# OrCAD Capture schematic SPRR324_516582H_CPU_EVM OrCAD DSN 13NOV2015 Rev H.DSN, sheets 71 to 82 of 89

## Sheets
71 SH78 - TPS57112 -- 1V5 DDR: size B; rev: A; company: Texas Instruments; note: 516172-0001
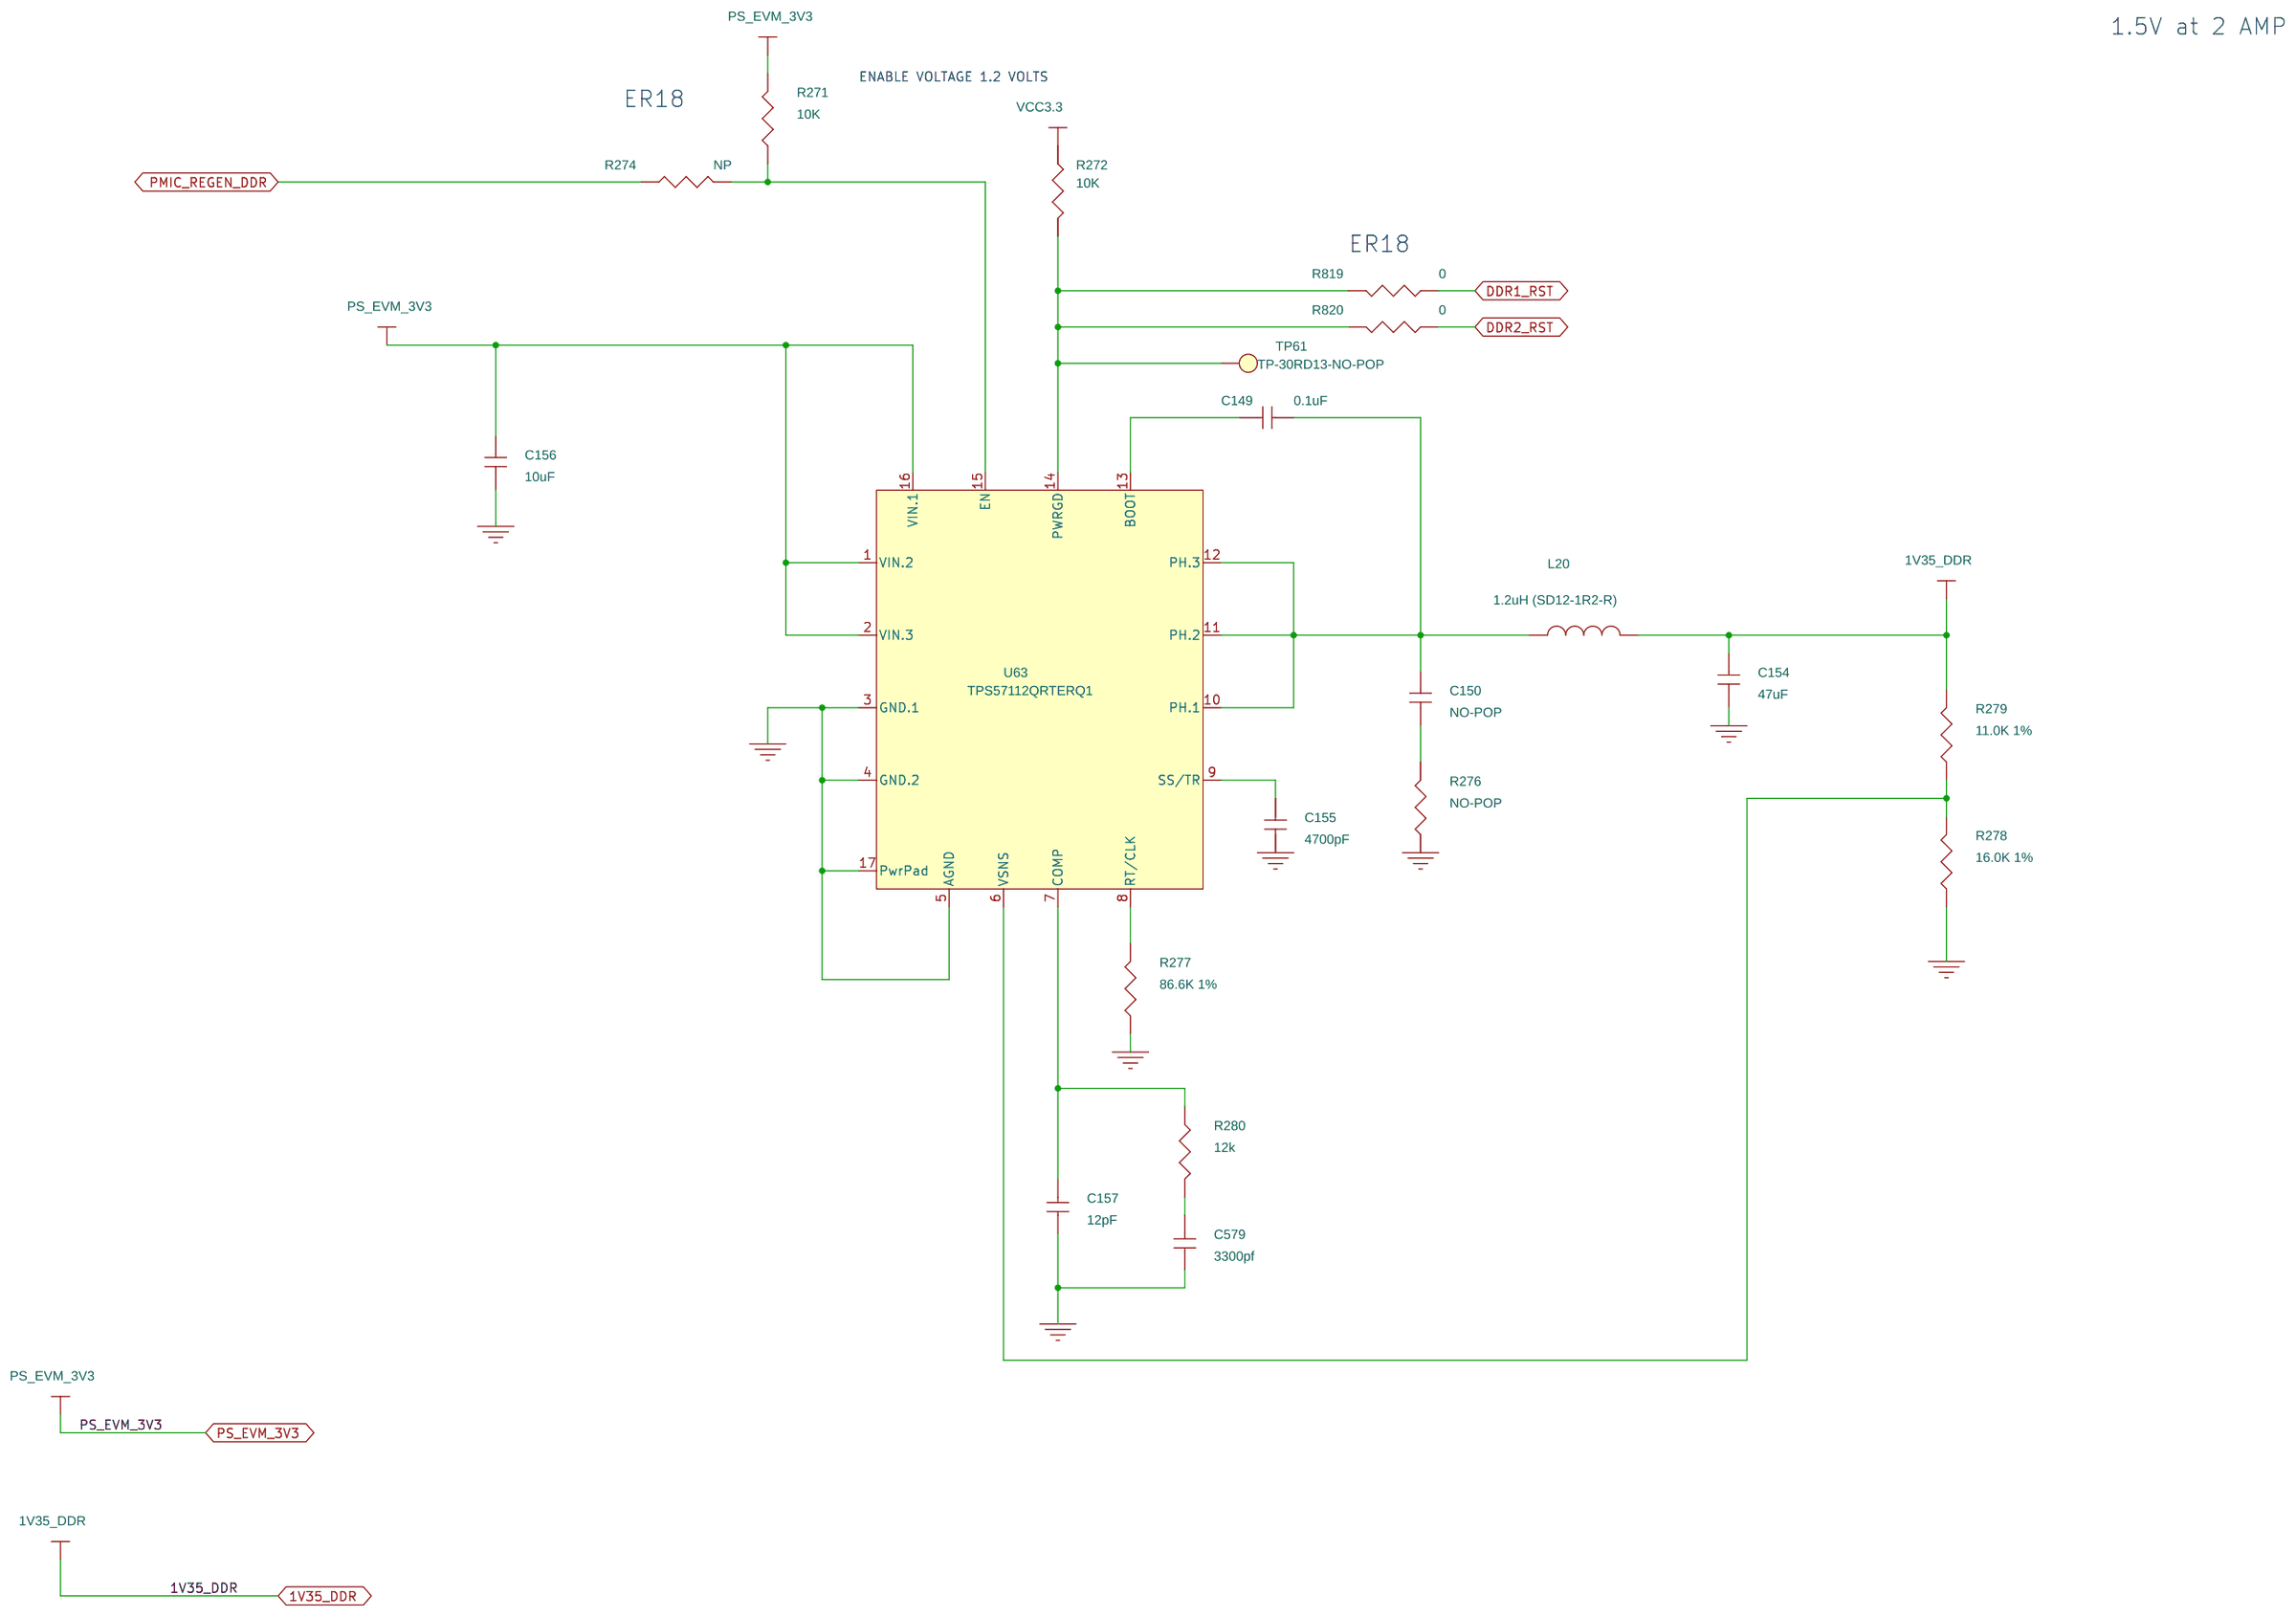
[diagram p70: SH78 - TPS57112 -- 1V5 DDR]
72 SH79 - CORE POWER ROUTER: size B
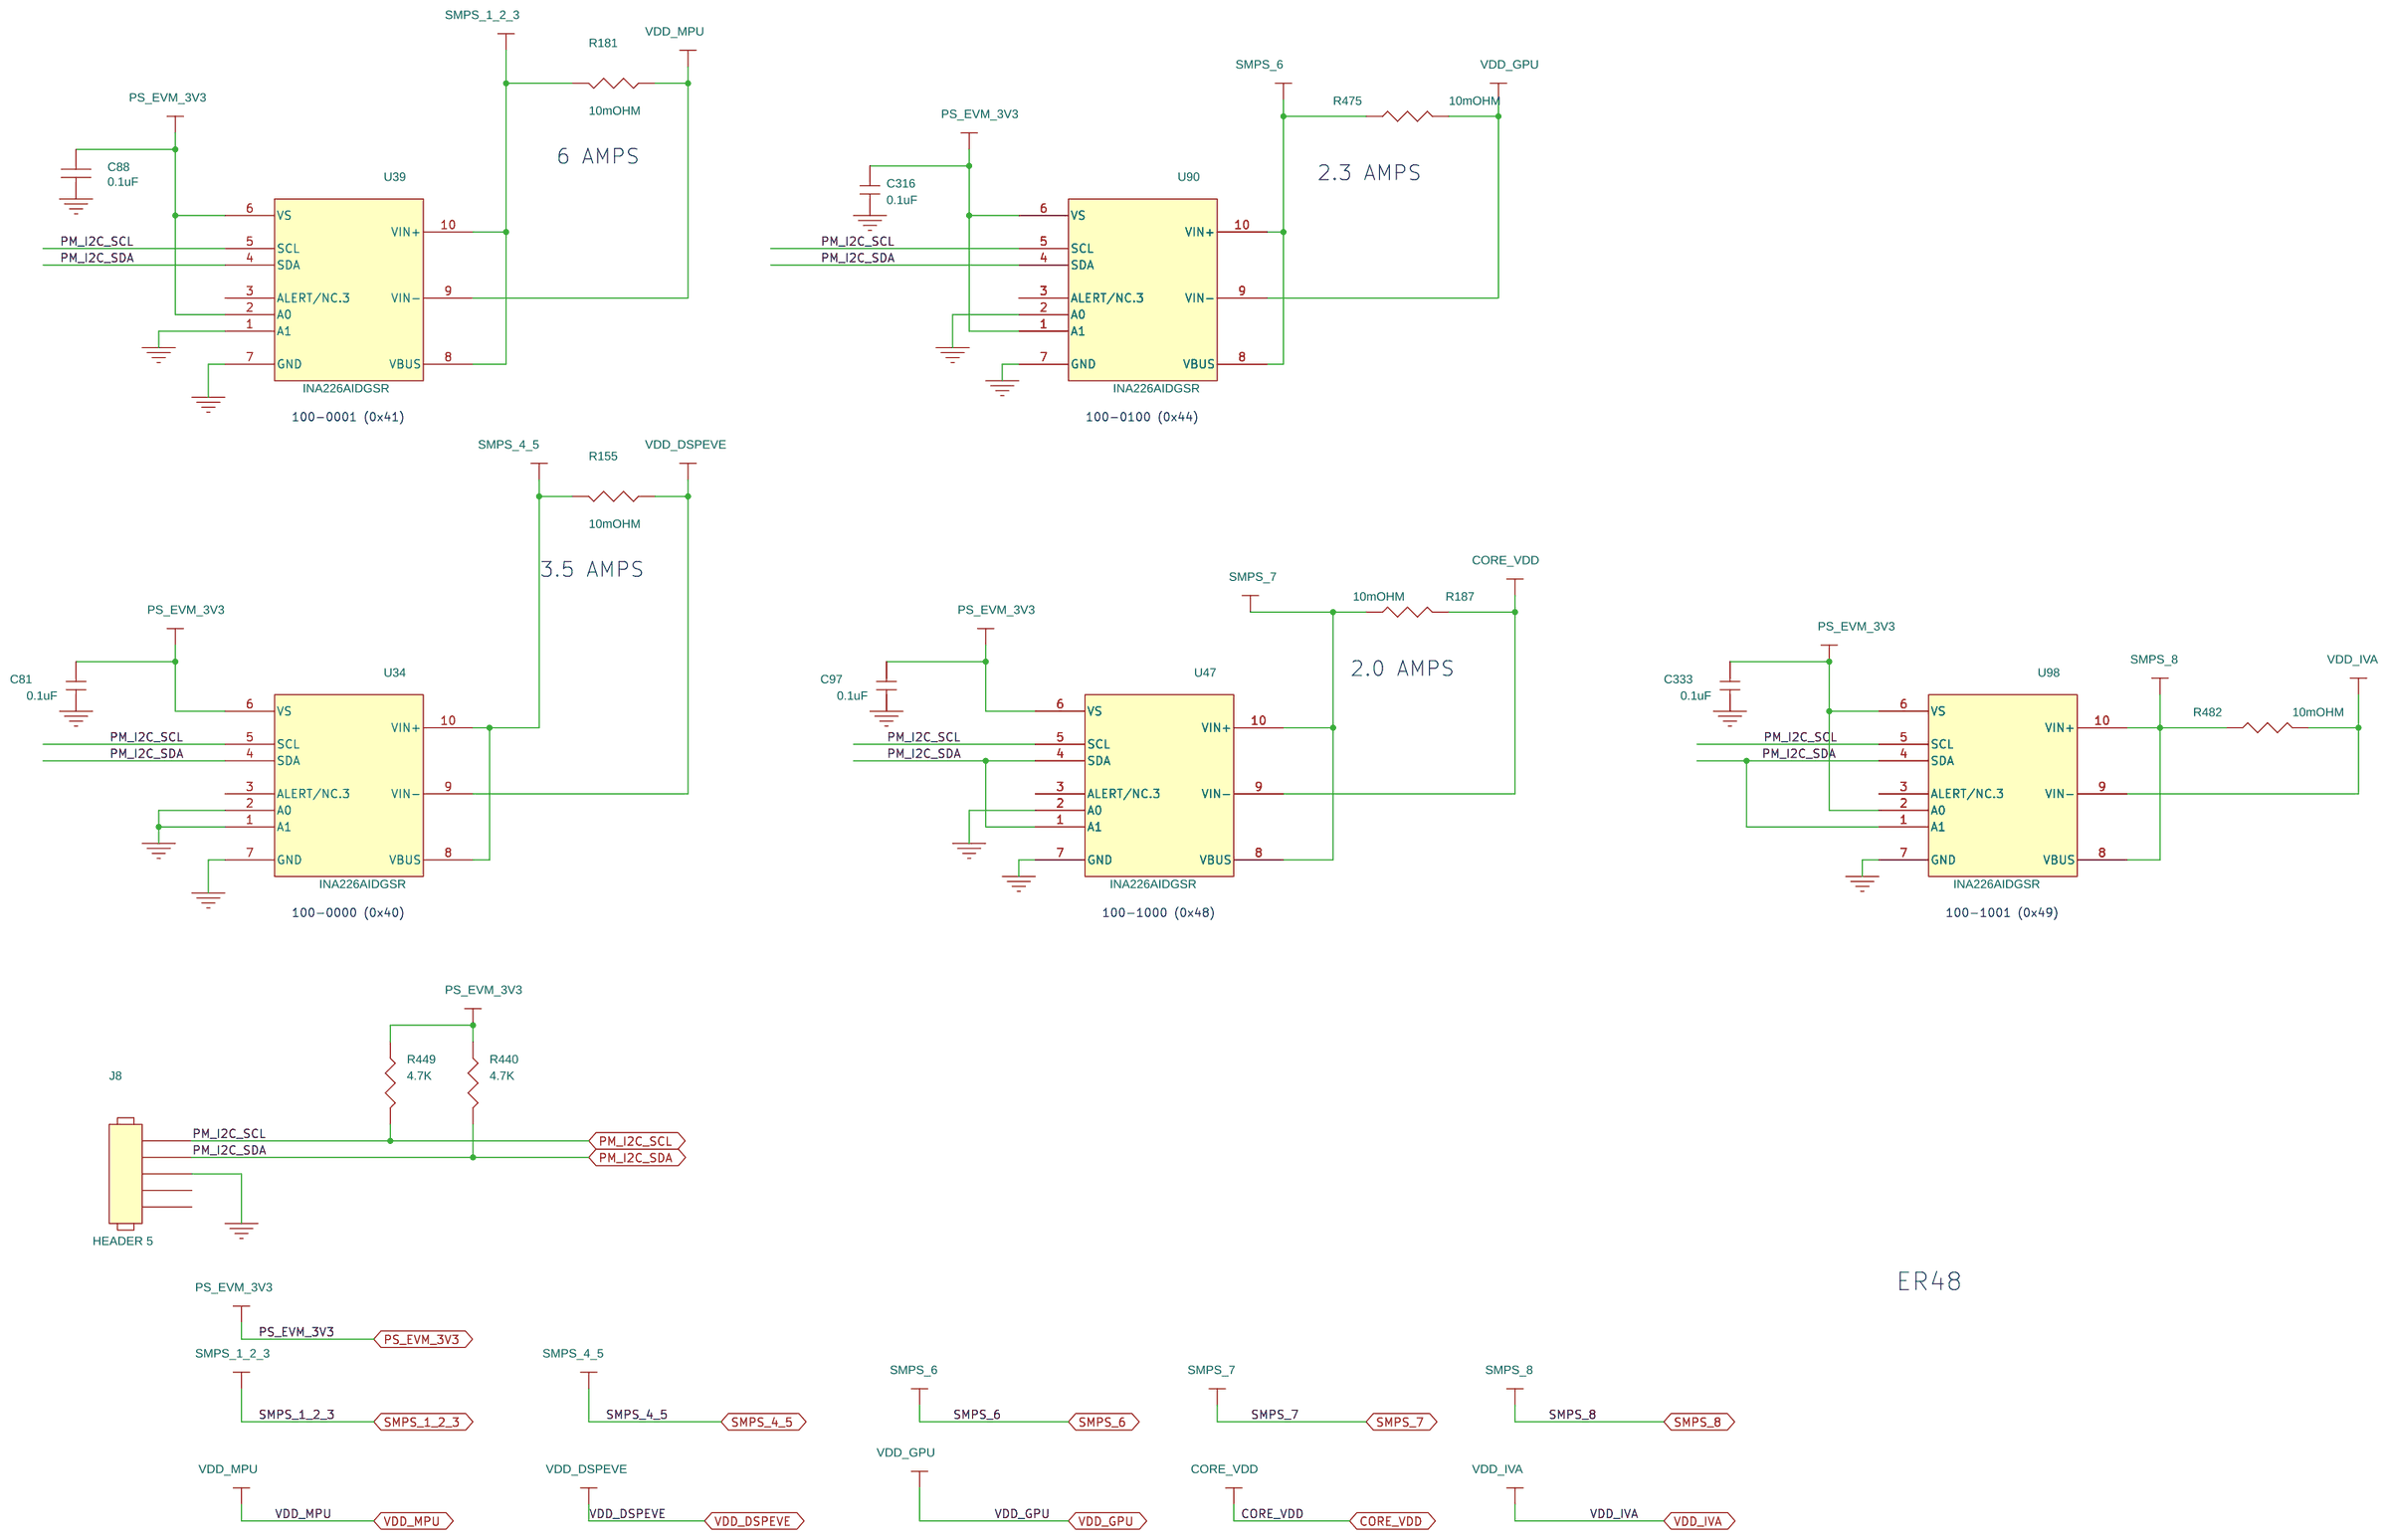
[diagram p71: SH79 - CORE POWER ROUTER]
73 SH80 - POWER ROUTER DDR: size B
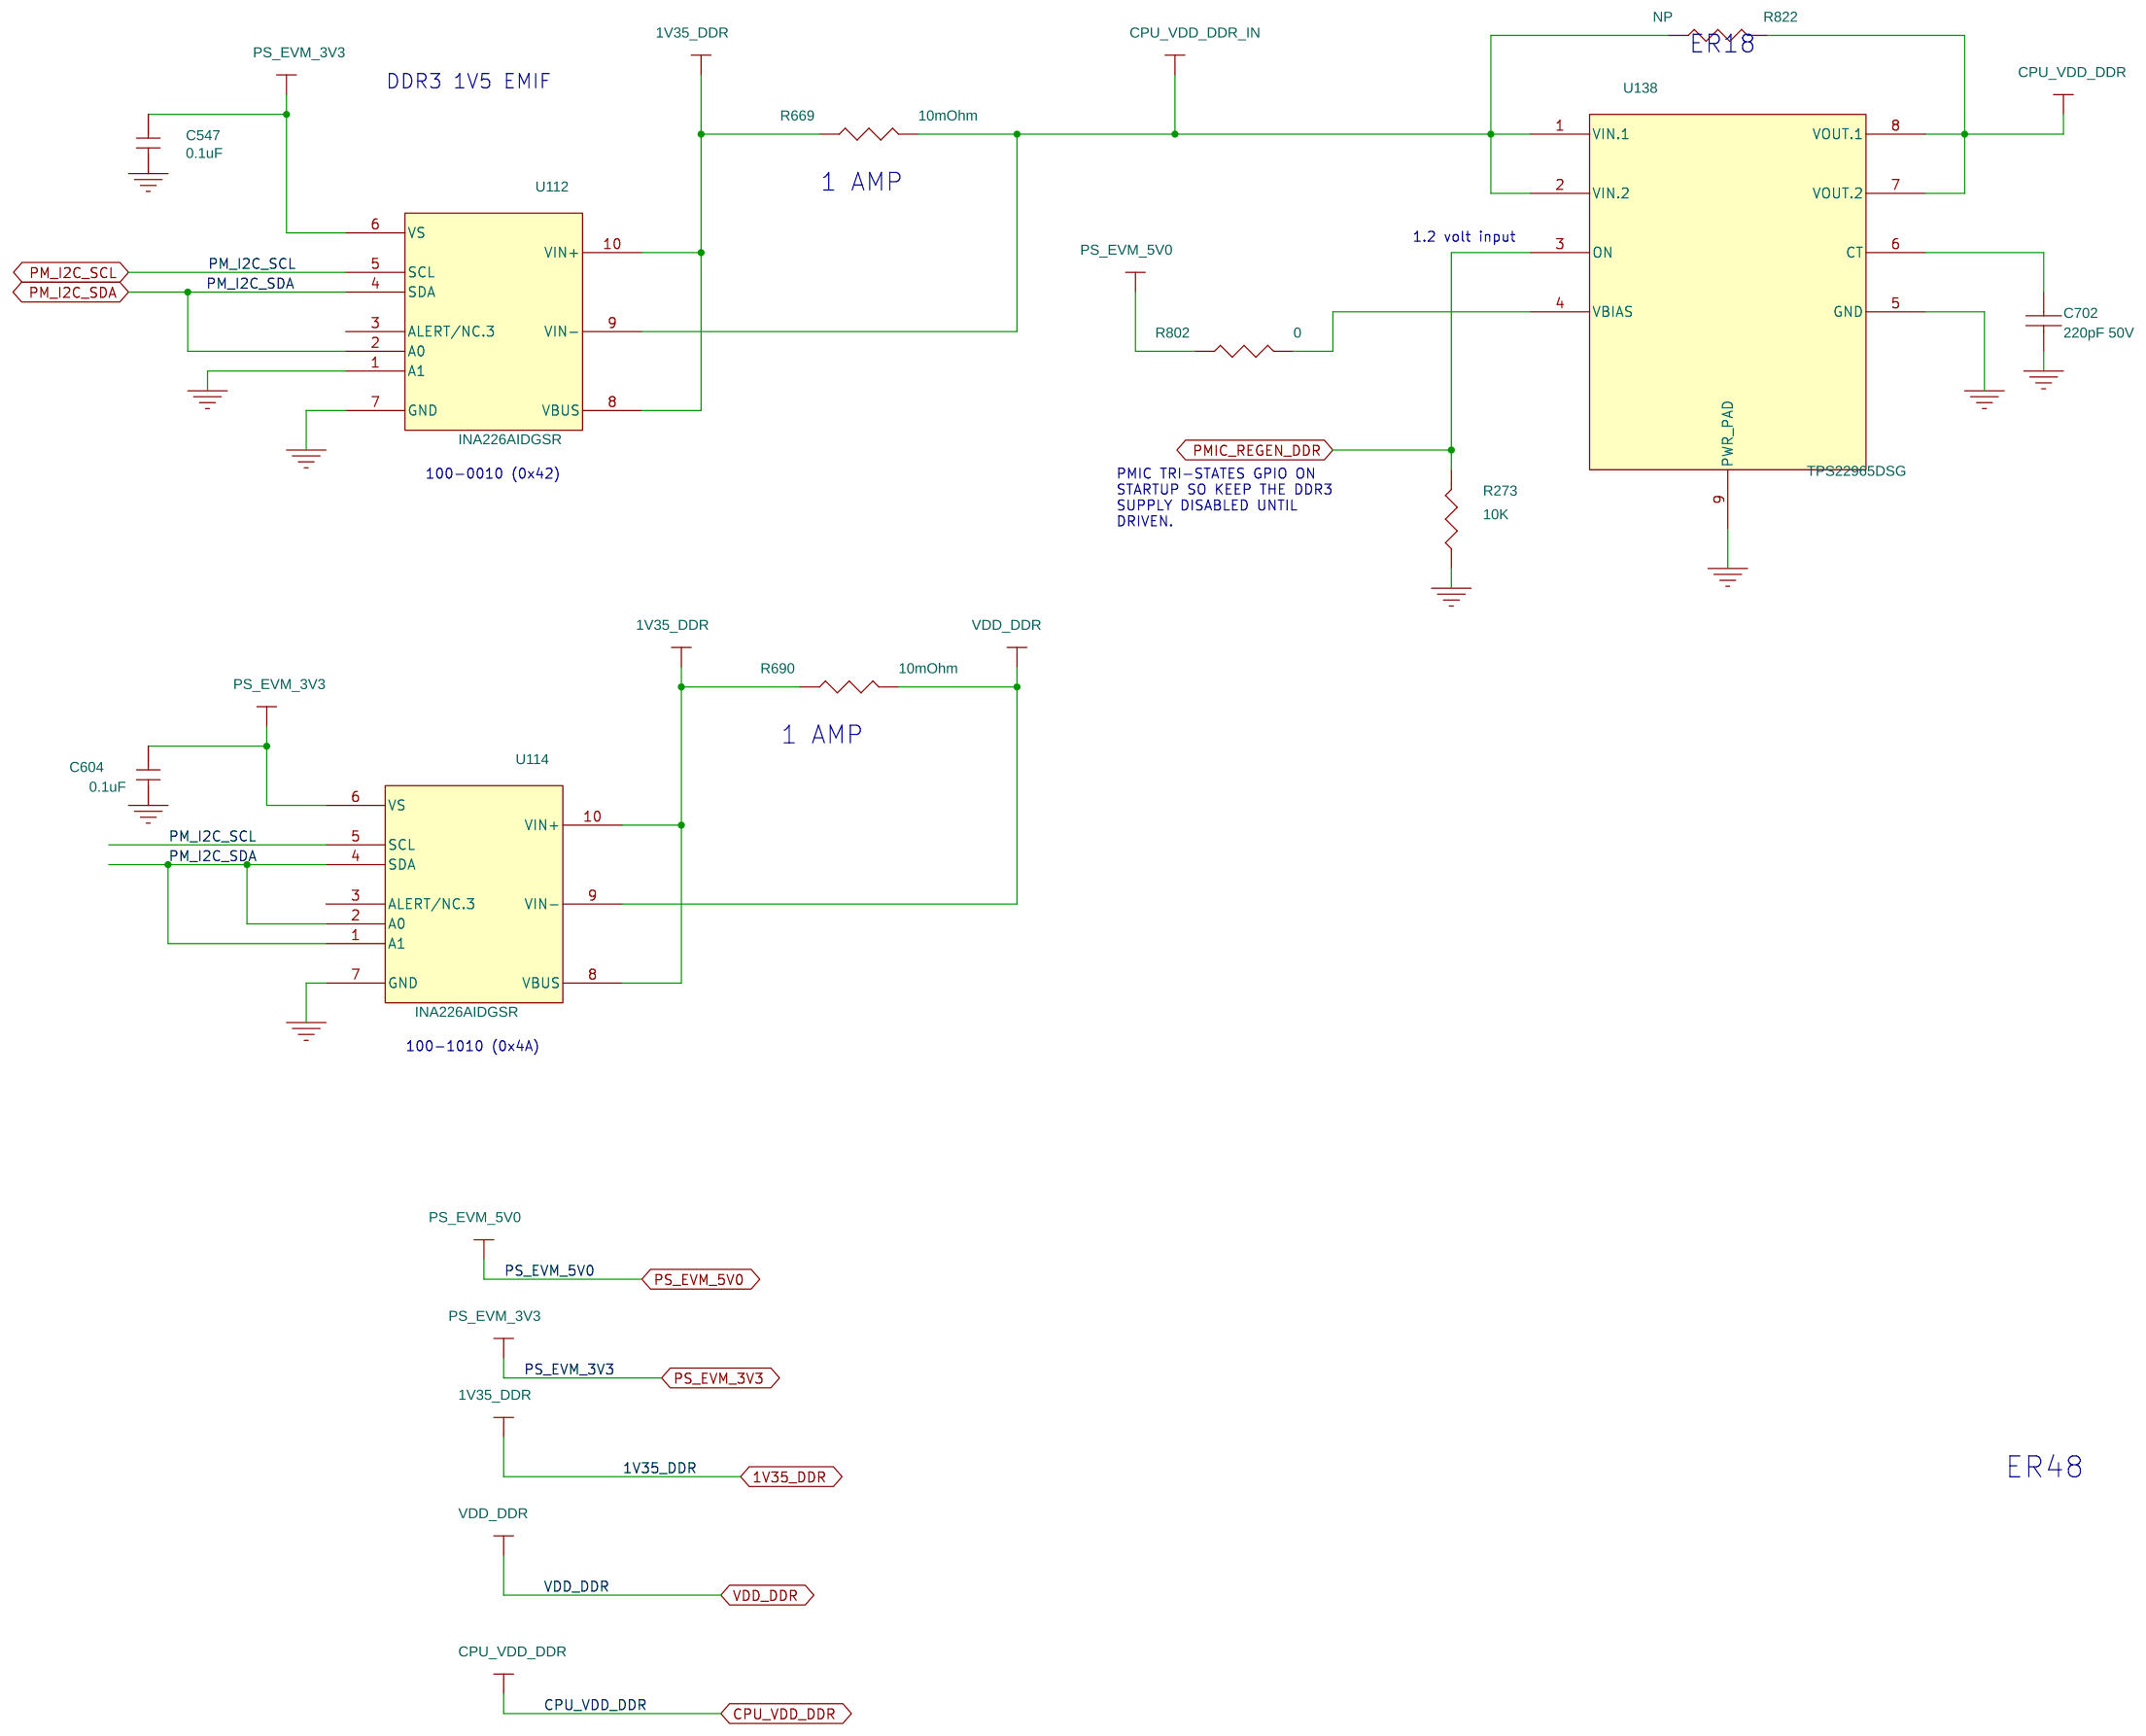
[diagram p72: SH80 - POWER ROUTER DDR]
74 SH81 - POWER ROUTER 1V8: size B; rev: G4
75 SH82 - POWER ROUTER 1V8A: size B; rev: G4
76 SH83 - POWER ROUTER RTC: size B; rev: A
77 SH84 - POWER ROUTER 3V3: size B
78 SH85 - POWER ROUTER EVM: size B
79 SH86 - RESET: size B; rev: D1
80 SH87 - POWER INPUT: size B
81 SH88 - POWER MONITOR I2C ADD: size B
82 SH89 - CHANGES REV H: rev: G4

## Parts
sheet SH78 - TPS57112 -- 1V5 DDR
C149  0.1uF  [c402-25]
C150  NO-POP  [c402-25]
C154  47uF  [C1206-40X70]
C155  4700pF  [c402-25]
C156  10uF  [C1206-40X70]
C157  12pF  [c402-25]
C579  3300pf  [c402-25]
L20  1.2uH (SD12-1R2-R)  [sd12-202x60]
R271  10K  [r402-25]
R272  10K  [r402-25]
R274  NP  [r402-25]
R276  NO-POP  [r603-35X45]
R277  86.6K 1%  [r402-25]
R278  16.0K 1%  [r402-25]
R279  11.0K 1%  [r402-25]
R280  12k  [r402-25]
R819  0  [r402-25]
R820  0  [r402-25]
TP61  TP-30RD13-NO-POP  [tp-30RD13]
U63  TPS57112QRTERQ1  [rte16-12x34]
sheet SH79 - CORE POWER ROUTER
C81  0.1uF  [c402-25]
C88  0.1uF  [c402-25]
C97  0.1uF  [c402-25]
C316  0.1uF  [c402-25]
C333  0.1uF  [c402-25]
J8  HEADER 5  [JUMP1X5-6040]
R155  10mOHM  [r2725-125x250]
R181  10mOHM  [r2725-125x250]
R187  10mOHM  [R1206-40x70]
R440  4.7K  [r402-25]
R449  4.7K  [r402-25]
R475  10mOHM  [R2512]
R482  10mOHM  [R1206-40x70]
U34  INA226AIDGSR  [dgs10-11x60]
U39  INA226AIDGSR  [dgs10-11x60]
U47  INA226AIDGSR  [dgs10-11x60]
U90  INA226AIDGSR  [dgs10-11x60]
U98  INA226AIDGSR  [dgs10-11x60]
sheet SH80 - POWER ROUTER DDR
C547  0.1uF  [c402-25]
C604  0.1uF  [c402-25]
C702  220pF 50V  [c603-35x45]
R273  10K  [r402-25]
R669  10mOhm  [R2512]
R690  10mOhm  [R2512]
R802  0  [r603-35x45]
R822  NP  [r1206-40X70]
U112  INA226AIDGSR  [dgs10-11x60]
U114  INA226AIDGSR  [dgs10-11x60]
U138  TPS22965DSG  [dsg8-11x20]
sheet SH81 - POWER ROUTER 1V8
C317  0.1uF  [c402-25]
R149  0.01  [R2512]
R476  0.01  [R2512]
U91  INA226AIDGSR  [dgs10-11x60]
sheet SH82 - POWER ROUTER 1V8A
C114  0.1uF  [c402-25]
C320  0.1uF  [c402-25]
R214  0.01  [r1206-40X70]
R477  0.01  [r1206-40X70]
U51  INA226AIDGSR  [dgs10-11x60]
U97  INA226AIDGSR  [dgs10-11x60]
sheet SH83 - POWER ROUTER RTC
R227  0.01  [r1206-40X70]
R606  0.01  [r1206-40X70]
R607  0.01  [r1206-40X70]
sheet SH84 - POWER ROUTER 3V3
C121  0.1uF  [c402-25]
C334  0.1uF  [c402-25]
E7  NFM21PC474R1C3D  [emi-NFM21p]
E8  NFM21PC474R1C3D  [emi-NFM21p]
R180  10mOHM  [r2725-125x250]
R219  0.01  [r1206-40X70]
R226  0.01  [r1206-40X70]
R275  0  [r1206-40X70]
U38  INA226AIDGSR  [dgs10-11x60]
U53  INA226AIDGSR  [dgs10-11x60]
sheet SH85 - POWER ROUTER EVM
R150  0  [r1206-40X70]
R156  10mOHM  [r2725-125x250]
R185  0.01  [R2512]
R228  0.01  [r1206-40X70]
R478  NO-POP  [r1206-40X70]
R608  0.01  [r1206-40X70]
sheet SH86 - RESET
C329  NO-POP  [c402-25]
C330  0.1uF  [c402-25]
C348  NO-POP  [c402-25]
C358  0.1uF  [c402-25]
C421  220pF  [c402-25]
C441  0.1uF  [c402-25]
C476  220pF  [c402-25]
C499  0.1uF  [c402-25]
C533  .1uF  [c201-6p6spc]
R151  0  [r402-25]
R152  10K  [r402-25]
R153  10K  [r402-25]
R529  10K  [r402-25]
R530  10K  [r402-25]
R531  0  [r402-25]
R554  0  [r402-25]
R555  NO-P0P  [r402-25]
R583  10K  [r402-25]
R596  10K  [r402-25]
R616  10K  [r402-25]
R623  10K  [r402-25]
R630  1K  [r201-6p6spc]
R631  1K  [r201-6p6spc]
R821  0  [r402-25]
R825  10K  [r402-25]
SW4  PB_SW  [SW4-7914G]
SW6  PB_SW  [SW4-7914G]
SW7  PB_SW  [SW4-7914G]
U37  TPS3808G09DBVR  [DBV6-27X39-6]
U44  TPS3808G09DBVR  [DBV6-27X39-6]
U102  TPS3808G09DBVRG4  [DBV6-27X39-6]
U107  TPS3808G09DBVRG4  [DBV6-27X39-6]
U141  TPS3808G09DBVR  [DBV6-27X39-6]
U142  SN74LVC2G74DCT  [dct8-14x70]
sheet SH87 - POWER INPUT
C45  0.1uF  [c603-35x45]
C47  1uF  [c805-35x60]
C49  0.1uF  [c603-35x45]
C50  1uF  [c805-35x60]
C52  4.7uF  [c1210-70x102]
C706  2.2uF 25V X7R  [c805-35x60]
C707  0.22uF  [c603-35x45]
D1  SMCJ30A-13-F  [SMC-80X128]
D2  SMCJ14A-13-F  [SMC-80X128]
DS5  LED_GRN  [led1206-59x59]
F1  8A_QuickBlow  [FUSEFOLDER-OMNI-BLOK]
J3  PJ-063BH  [pwrjack-cui-pj063bh]
J4  HEADER 2  [JUMP1X2-6040]
J7  HEADER 2  [JUMP1X2-6040]
Q5  CSD18501Q5A  [pwr-q5a-slps319]
R775  1K  [r402-25]
R810  1K  [r402-25]
SW9  PB_SW  [SW4-7914G]
TP3  TESTPOINT  [tp1-6040]
TP4  TESTPOINT  [tp1-6040]
TP62  TESTPOINT  [tp1-6040]
TP63  TESTPOINT  [tp1-6040]
TP823  SMT-TP  [TP1-70X135]
TP824  SMT-TP  [TP1-70X135]
TP825  SMT-TP  [TP1-70X135]
TP826  SMT-TP  [TP1-70X135]
TP827  SMT-TP  [TP1-70X135]
TP828  SMT-TP  [TP1-70X135]
TP829  SMT-TP  [TP1-70X135]
TP830  SMT-TP  [TP1-70X135]
TP831  TP_0  [tp1-18rd8]
U8  LM74610  [dgk8-14x70]
sheet SH88 - POWER MONITOR I2C ADD
J18  AXT340124  [conn-axt40]

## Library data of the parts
C81 C97 C114 C121 C149 C316 C317 C320 C333 C334 C547 C604 = CAP_NP: Part #: 101587-1100R
C150 = CAP_NP: Part #: C0402-NOPOP
C154 = CAP_NP: Part #: 101497-0471R
C155 = CAP_NP: Part #: 103217-1472R
C156 = CAP_NP: Part #: 101497-0101R
C157 = CAP_NP: Part #: 101782-1124R
C579 = CAP_NP: Part #: 102058-1332R
L20 = INDUCTOR: Part #: 103025-0120R
R152 R153 R271-R273 R529 R530 R825 = R: Part #: 101370-1003R
R274 = R: Part #: R0402-NOPOP
R276 = R: Part #: R0603-NOPOP
R277 = R: Part #: 102145-8663R
R278 = R: Part #: 102145-1603R
R279 = R: Part #: 102145-1103R
R280 = R: Part #: 102145-1203R
R151 R531 R554 R819-R821 = R: Part #: 101370-0001R
TP61 = TESTPOINT
U63 = TPS57112QRTERQ1_0: Part #: 103994-0001R
C88 C330 C358 = CAP: Part #: 101587-1100R
J8 = HEADER_5: Part #: 100115-0005R
R155 R156 R180 R181 = RESISTOR: Part #: 101396-0001R
R187 R214 R219 R226-R228 R477 R482 R606-R608 = R: Part #: 102598-0001R
R440 R449 = R: Part #: 101370-4702R
R149 R185 R475 R476 R669 R690 = R: Part #: 101396-0001R
U34 U38 U39 U47 U51 U53 U90 U91 U97 U98 U112 U114 = INA220IDCN_0: Part #: 103928-0001R
C702 = CAP: Part #: 100993-1223R
R802 = R: Part #: 100687-0001R
R822 = R: Part #: r1206-nopop
U138 = TPS22965DSG: Part #: 104267-0001R
E7 E8 = NFM_1: Part #: 102569-1470R
R150 R275 = R: Part #: 100155-0001R
R478 = R: Part #: R1206-NOPOP
C329 C348 = CAP: Part #: C0402-NOPOP
C421 C476 = CAP_NP_2: Part #: 101782-1223R
C441 C499 = CAP_NP_2: Part #: 101587-1100R
C533 = CAP: Part #: 103241-1100R
R555 = R_2: Part #: R0402-NOPOP
R583 R616 = RESISTOR: Part #: 101370-1003R
R596 R623 = R_2: Part #: 101370-1003R
R630 R631 = R: Part #: 103158-1002R
SW4 SW6 SW7 SW9 = SW_PUSHBUTTON_3: Part #: 101023-0001R
U37 U44 U102 U107 U141 = TPS3808G09DBVR_0: Part #: 102020-0009R
U142 = SN74LVC2G74DCT: Part #: 103304-0001R
C45 C49 = CAP_NP: Part #: 100993-1100R
C47 C50 = CAP_NP: Part #: 100201-0100R
C52 = CAP_NP: Part #: 103058-0470R
C706 = CAP_NP_0: Part #: 101415-0220R
C707 = CAP: Part #: 103885-1220R
D1 = Diode_SMCJ15CA: Part #: 101808-0030R
D2 = Diode_SMCJ15CA: Part #: 101808-0014R
DS5 = LED_RED_0: Part #: 100823-0001R
F1 = NANO-SMF_0: Part #: 102110-0008R
J3 = PWR_JACK_0: Part #: 104303-0001R
J4 = HEADER_2: Part #: 100115-0002R
J7 = HEADER_2: Part #: NO-POP
Q5 = MOSFET_CSD16406Q3_0: Part #: 104283-0001R
R775 R810 = R_2: Part #: 102145-1002R
TP3 TP4 TP62 TP63 = TESTPOINT: Part #: 100115-0001R
TP823-TP830 = SMT-TP: Part #: 104178-0001R
TP831 = TP_0: Part #: TP-18RD8-NO-POP
U8 = LM74610: Part #: 104635-0001R
J18 = CONN_AXT340124_40PINS_SMT_X: Part #: 104610-0040R

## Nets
1V35_DDR: C154.1 J18.33 J18.37 L20.2 R272.1 R279.2 R669.1 R690.1 U112.8(VBUS) U112.10(VIN+) U114.8(VBUS) U114.10(VIN+) ; also on sheet 70
GND: C45.2 C47.2 C49.2 C50.2 C52.2 C81.2 C88.2 C97.2 C114.2 C121.2 C154.2 C155.2 C156.2 C157.1 C316.2 C317.2 C320.2 C329.2 C330.2 C333.2 C334.2 C348.2 C358.2 C421.2 C441.2 C476.2 C499.2 C533.2 C547.2 C579.1 C604.2 C702.2 C707.2 D2.1(CATHODE) DS5.1(cathode) E7.2 E8.2 J3.2 J3.MTG1 J3.MTG2 J4.1 J7.2 J8.3 J18.41 J18.42 J18.43 J18.44 R152.2 R273.1 R276.1 R277.1 R278.1 R529.2 R555.1 R630.2 R810.2 SW4.1(A) SW4.2(AA) SW6.1(A) SW6.2(AA) SW7.1(A) SW7.2(AA) TP3.1(TP) TP4.1(TP) TP62.1(TP) TP63.1(TP) TP823.1 TP824.1 TP825.1 TP826.1 TP827.1 TP828.1 TP829.1 TP830.1 U34.1(A1) U34.2(A0) U34.7(GND) U37.2(GND) U38.7(GND) U39.1(A1) U39.7(GND) U44.2(GND) U47.2(A0) U47.7(GND) U51.1(A1) U51.7(GND) U53.7(GND) U63.3(GND.1) U63.4(GND.2) U63.5(AGND) U63.17(PwrPad) U90.2(A0) U90.7(GND) U91.7(GND) U97.7(GND) U98.7(GND) U102.2(GND) U107.2(GND) U112.1(A1) U112.7(GND) U114.7(GND) U138.5(GND) U138.9(PWR_PAD) U141.2(GND) U142.2(D) U142.4(GND) ; also on sheet 3 4 5 7 8 9 10 11 13 15 16 17 18 19 20 21 24 25 26 27 28 29 30 31 32 33 34 35 36 37 38 39 40 42 43 46 47 49 50 51 52 53 54 55 56 57 58 60 61 62 63 64 65 66 67 68 69 70 84 85 86 87 88 89
VDD_CDCM9102: E7.3 ; also on sheet 30
VDD_DDR: J18.35 R690.2 U114.9(VIN-) ; also on sheet 42 43 44 46 47 48
VDD_DSPEVE: J18.4 R155.1 U34.9(VIN-) ; also on sheet 39 65
VDD_GPU: J18.12 R475.2 U90.9(VIN-) ; also on sheet 39 66
VDD_IVA: J18.16 R482.2 U98.9(VIN-) ; also on sheet 39 66
VDD_MPU: J18.20 R181.1 R554.1 U39.9(VIN-) ; also on sheet 39 65
VDD_RTC: R531.1 R606.2 ; also on sheet 33
VDDA_1V8_PHY: R477.1 U97.9(VIN-) ; also on sheet 13 21 89
VDDA_1V8_PLL: R214.1 U51.9(VIN-) ; also on sheet 33 38
VDDA_RTC: R227.1 ; also on sheet 33
VDDS18V: R476.2 U91.9(VIN-) ; also on sheet 11 35 36 66
VDDSHV: J18.24 R180.1 U38.9(VIN-) ; also on sheet 35
VDDSHV5: R530.1 R607.1 ; also on sheet 3 33
VDDSHV8: R228.1 ; also on sheet 35
VIN_CONN: F1.2 J3.1 ; also on sheet 67
BCK2_3V3: R275.1 ; also on sheet 33
CORE_VDD: J18.8 R187.1 U47.9(VIN-) ; also on sheet 39 66
CPU_POR_RESETn: R596.1 U102.1(~{RESE}T) ; also on sheet 33
CPU_RESETn: R623.1 U107.1(~{RESE}T) ; also on sheet 33
CPU_VDD_DDR: R822.1 U138.7(VOUT.2) U138.8(VOUT.1) ; also on sheet 19 20 37
CPU_VDD_DDR_IN: J18.39 R669.2 R822.2 U112.9(VIN-) U138.1(VIN.1) U138.2(VIN.2)
DDR1_RST: R819.1 ; also on sheet 19 42
DDR2_RST: R820.1 ; also on sheet 20 46
EVM_1V8: R149.2 ; also on sheet 8 10 26 52 53 61 69
EVM_3V3: R156.1 R478.2 ; also on sheet 3 4 5 7 8 9 10 11 14 15 16 17 18 24 25 26 27 28 29 30 31 32 33 49 50 51 52 53 56 57 58 60 61 69 70 84 85 86 87 88
EVM_3V3_SW: J18.22 R156.2 R180.2 R226.2 U38.8(VBUS) U38.10(VIN+) ; also on sheet 68
EVM_5V0: R150.2 R185.2 ; also on sheet 3 26 27 29 31 49 54 61
EVM_12V: C45.1 C47.1 C49.1 C50.1 C52.1 J7.1 Q5.5(D1) R775.2 U8.8(CATHODE) ; also on sheet 11 31 61 67
LDO1_OUT: R228.2 R608.2 ; also on sheet 64
LDO2_OUT: R607.2 ; also on sheet 64
LDO3_OUT: R477.2 U97.8(VBUS) U97.10(VIN+) ; also on sheet 64
LDO9_OUT: R606.1 ; also on sheet 64
LDOLN_OUT: R214.2 U51.8(VBUS) U51.10(VIN+) ; also on sheet 64
LDOUSB_OUT: R219.2 U53.8(VBUS) U53.10(VIN+) ; also on sheet 64
MMC1_3V3: R608.1 ; also on sheet 10
PB_ON: J4.2 SW9.3(B) SW9.4(BB) ; also on sheet 67
PGD_3V3_5V0: R821.1 ; also on sheet 67
PM_I2C_SCL: J8.1 R449.2 U34.5(SCL) U38.2(A0) U38.5(SCL) U39.5(SCL) U47.5(SCL) U51.2(A0) U51.5(SCL) U53.5(SCL) U90.5(SCL) U91.5(SCL) U97.2(A0) U97.5(SCL) U98.5(SCL) U112.5(SCL) U114.5(SCL)
PM_I2C_SDA: J8.2 R440.2 U34.4(SDA) U38.4(SDA) U39.4(SDA) U47.1(A1) U47.4(SDA) U51.4(SDA) U53.4(SDA) U90.4(SDA) U91.2(A0) U91.4(SDA) U97.1(A1) U97.4(SDA) U98.1(A1) U98.4(SDA) U112.2(A0) U112.4(SDA) U114.1(A1) U114.2(A0) U114.4(SDA)
PMIC_REGEN_DDR: R273.2 R274.1 U138.3(ON) ; also on sheet 63
PMIC_RESET_IN: R153.2 U37.1(~{RESE}T) ; also on sheet 63
POWERHOLD: U142.5(Q) ; also on sheet 63
POWERHOLD_CLK: R630.1 U142.1(CLK) ; also on sheet 87
PS_EVM_3V3: C81.1 C88.1 C97.1 C114.1 C121.1 C156.1 C316.1 C317.1 C320.1 C330.1 C333.1 C334.1 C358.1 C441.1 C499.1 C533.1 C547.1 C604.1 R151.1 R153.1 R271.2 R275.2 R440.1 R449.1 R583.1 R596.2 R616.1 R623.2 R631.1 R825.1 U34.6(VS) U37.6(VDD) U38.1(A1) U38.6(VS) U39.2(A0) U39.6(VS) U44.6(VDD) U47.6(VS) U51.6(VS) U53.1(A1) U53.2(A0) U53.6(VS) U63.1(VIN.2) U63.2(VIN.3) U63.16(VIN.1) U90.1(A1) U90.6(VS) U91.1(A1) U91.6(VS) U97.6(VS) U98.2(A0) U98.6(VS) U102.6(VDD) U107.6(VDD) U112.6(VS) U114.6(VS) U141.5(SENSE1) U141.6(VDD) U142.6(CLR) U142.8(VCC) ; also on sheet 31 63 64 65 66 67 68 69 70
PS_EVM_5V0: R185.1 R802.1 ; also on sheet 10 64 67 68 69
PWR_CBT: R150.1 R478.1 ; also on sheet 25
RTC_PORZ: R530.2 U44.1(~{RESE}T) ; also on sheet 33
SMPS_1_2_3: J18.18 R181.2 U39.8(VBUS) U39.10(VIN+) ; also on sheet 65
SMPS_4_5: J18.2 R155.2 U34.8(VBUS) U34.10(VIN+) ; also on sheet 65
SMPS_6: J18.10 R475.1 U90.8(VBUS) U90.10(VIN+) ; also on sheet 66
SMPS_7: J18.6 R187.2 U47.8(VBUS) U47.10(VIN+) ; also on sheet 66
SMPS_8: J18.14 R482.1 U98.8(VBUS) U98.10(VIN+) ; also on sheet 66
SMPS_9: R149.1 R476.1 U91.8(VBUS) U91.10(VIN+) ; also on sheet 66
TPS43351_GC2: TP831.1 ; also on sheet 67
VDAC_3V3: E8.3 ; also on sheet 55 63
VRTC_OUT: R227.2 ; also on sheet 63 64
VUSB_3V3: R219.1 U53.9(VIN-) ; also on sheet 13
N18740603: C157.2 R280.1 U63.7(COMP)
N18740978: R278.2 R279.1 U63.6(VSNS)
N18743331: C149.2 U63.13(BOOT)
N18743657: R271.1 R274.2 U63.15(EN)
N18763016: R277.2 U63.8(RT/CLK)
N18763017: C155.1 U63.9(SS/TR)
N18763019: C149.1 C150.1 L20.1 U63.10(PH.1) U63.11(PH.2) U63.12(PH.3)
N18763021: R272.2 R819.2 R820.2 TP61.1(TP) U63.14(PWRGD)
N19176689: C579.2 R280.2
N19176787: C150.2 R276.2
N19793183: DS5.2(ANODE) R775.1
N21791938: R802.2 U138.4(VBIAS)
N21791974: C702.1 U138.6(CT)
N21953256: R810.1 SW9.1(A) SW9.2(AA)
N23160421: R554.2 R555.2 U102.5(SENSE1) U107.5(SENSE1)
N23221766: R583.2 R821.2 SW4.3(B) SW4.4(BB) U102.3(~{MR})
N23459932: R631.2 SW7.3(B) SW7.4(BB) U141.3(~{MR})
N23462461: R825.2 U141.1(~{RESE}T) U142.7(PRE)
N24007310: D1.2(ANODE) D2.2(ANODE)
N24007325: C707.1 D1.1(CATHODE) F1.1 Q5.1(S1) Q5.2(S2) Q5.3(S3) U8.4(ANODE)
N24007357: C706.2 U8.7(VCAPH)
N24007377: C706.1 U8.1(VCAPL)
N24007383: Q5.4(G) U8.2(GT_PULL_DWN) U8.6(GATE_DRV)
N24686365: R151.2 R152.1 U37.5(SENSE1)
N24686375: C329.1 U37.4(CT)
N24700307: C421.1 U102.4(CT)
N24700337: C476.1 U107.4(CT)
N24700536: R616.2 SW6.3(B) SW6.4(BB) U107.3(~{MR})
N26828582: E7.1 E8.1 R226.1
N43640412: R529.1 R531.2 U44.5(SENSE1)
N43640433: C348.1 U44.4(CT)

Not connected (* = marked no-connect by the designer): J8 4 5; J18 1 3 5 7 9 11 13 15 17 19 21 23 25 26 27 28 29 30 31 32 34 36 38 40; U8 3(NC3)* 5(NC5)*; U34 3(ALERT/NC.3); U37 3(~{MR}); U38 3(ALERT/NC.3); U39 3(ALERT/NC.3); U44 3(~{MR}); U47 3(ALERT/NC.3); U51 3(ALERT/NC.3); U53 3(ALERT/NC.3); U90 3(ALERT/NC.3); U91 3(ALERT/NC.3); U97 3(ALERT/NC.3); U98 3(ALERT/NC.3); U112 3(ALERT/NC.3); U114 3(ALERT/NC.3); U141 4(CT)*; U142 3(QN)*

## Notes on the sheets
sheet 71
- 1.5V at 2 AMP
- ENABLE VOLTAGE 1.2 VOLTS
- ER18
- ER18
sheet 72
- 6 AMPS
- 2.3 AMPS
- 100-0001 (0x41)
- 100-0100 (0x44)
- 3.5 AMPS
- 2.0 AMPS
- 100-0000 (0x40)
- 100-1000 (0x48)
- 100-1001 (0x49)
- ER48
sheet 73
- ER18
- DDR3 1V5 EMIF
- 1 AMP
- 1.2 volt input
- 100-0010 (0x42)
- PMIC TRI-STATES GPIO ON
  STARTUP SO KEEP THE DDR3
  SUPPLY DISABLED UNTIL
  DRIVEN.
- 1 AMP
- 100-1010 (0x4A)
- ER48
sheet 74
- 100-0110 (0x46)
sheet 75
- 100-0011 (0x43)
- 100-1011 (0x4B)
sheet 77
- ER48
- 100-0101 (0x45)
- 100-0111 (0x47)
sheet 78
- ER48
sheet 79
- REV D1
- ER27
- ER27
- REV D1
- ER14
- REV D
sheet 80
- VBATT
  12v
- Input
- for pushbutton
- ER27
- ER46
- OPTIONAL FAN CONNECTOR
- DISTRIBUTE ON BOARD, ONE GND TESTPOINT BY MLB CONNECTOR
sheet 81
- ER52
- ETHERNET STRAPPING
- DARA Bd Interface Connector
- DARA Bd can be interfaced to conduct more in-depth
  power measurements.
  All Vdiff signal pairs (P & N) shown should be routed as
  pseudo-Diff Pair segments using min trace widths since
  these are low voltage sensing nets, not power delivery nets.
- CLK_MAC_FREQ      Low  (25MHz) <-- CLK_TO_MAC is not used
  RGMII_SEL0        High (RGMII - 3COM)
  RGMII_SEL1        High (RGMII - 3COM)
  SPEED0_STRAP      Low  (all speeds ok)
  DUPLEX_STRAP      High (full duplex)
  AN_EN_STRAP       High (auto-negotiation enabled)
  SPEED1_STRAP      Low  (all speeds ok)
  VDD_SEL_STRAP     High (3.3V I/O)
  NON_IEEE_STRAP    High (allow IEEE non-compliant operation)
  MAN_MDIX_STRAP    Low  (straight through mode)
  MAC_CLK_EN_STRAP  Low  (disable CLK_TO_MAC output)
  MULTI_EN_STRAP    Low  (single endpoint during auto-negotiation)
  MDIX_EN_STRAP     High (auto MDIX pair swap enable)
- Vdiff, P
- Vdiff, P
- R155
- Vdiff, N
- Vdiff, N
- Vdiff, P
- Vdiff, P
- R187
- Vdiff, N
- Vdiff, N
- Vdiff, P
- Vdiff, P
- R475
- Vdiff, N
- Vdiff, N
- Vdiff, P
- Vdiff, P
- R482
- Vdiff, N
- Vdiff, N
- Vdiff, P
- Vdiff, P
- R181
- Vdiff, N
- Vdiff, N
- Vdiff, P
- Vdiff, P
- R180
- Vdiff, N
- Vdiff, N
- Vdiff, P
- Vdiff, P
- Vdiff, N
- Vdiff, N
- Vdiff, P
- Vdiff, P
- Vdiff, N
- Vdiff, N
- R690
- Vdiff, P
- GPIO
- Vdiff, N
- GPIO
- R669
- Vdiff, P
- GND
- Vdiff, N
- GND
